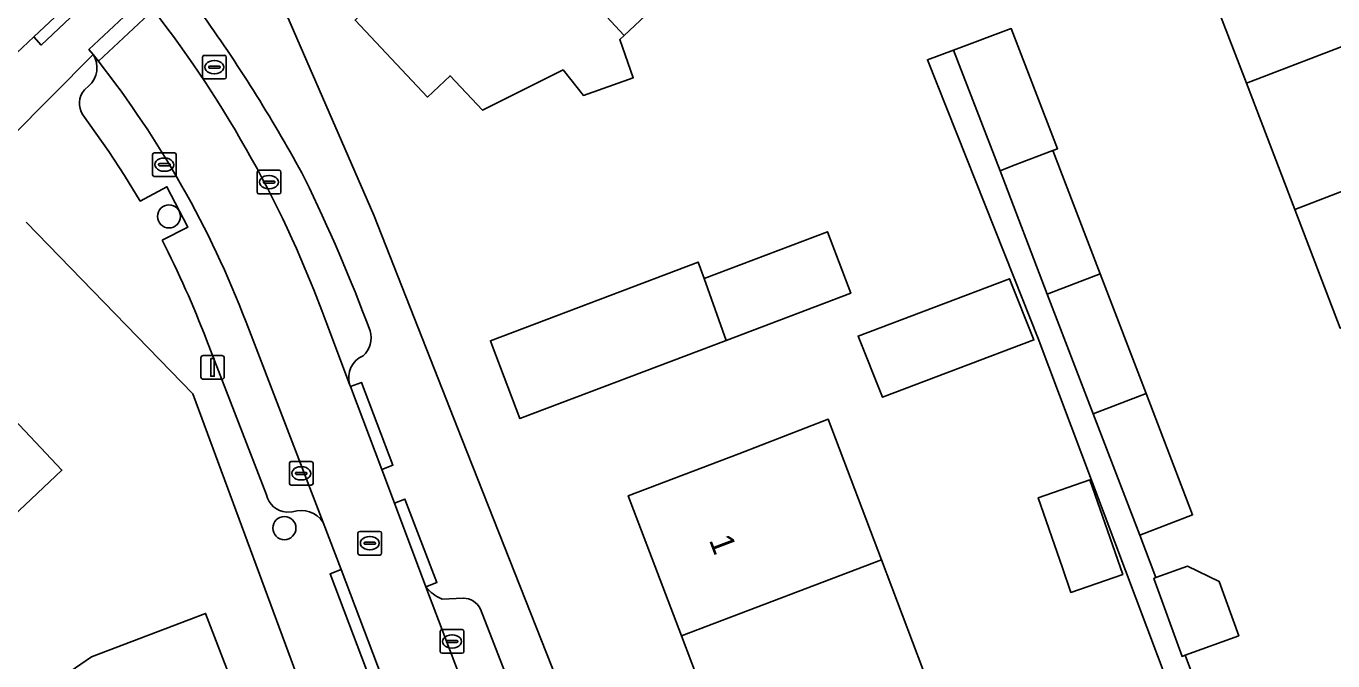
# Model space of a CAD drawing. Extents: x 159960 to 160866, y 382700 to 383354.
# Drawn here: x 160397.2 to 160452.4, y 383068.3 to 383095.2 of the extents above; entities that cross this region are included whole.
import ezdxf

# ---------------------------------------------------------------- set-up
doc = ezdxf.new("R2010")
doc.units = 0
for name, color, linetype in [('IMGEO_Boom', 7, 'Continuous'), ('IMGEO_Erf', 7, 'Continuous'), ('IMGEO_Kolk', 7, 'Continuous'), ('IMGEO_Lichtmast', 7, 'Continuous'), ('IMGEO_Pand', 7, 'Continuous'), ('IMGEO_Pand_nummerreeks', 7, 'Continuous'), ('IMGEO_Parkeervlak_open', 7, 'Continuous'), ('IMGEO_Rijbaan_lokaal_open', 7, 'Continuous'), ('IMGEO_Rioolput', 7, 'Continuous'), ('IMGEO_Voetpad_open', 7, 'Continuous')]:
    doc.layers.add(name, color=color, linetype=linetype)

msp = doc.modelspace()

# ---------------------------------------------------------------- linework, layer by layer
at = {"layer": 'IMGEO_Boom'}
for centre in [(160403.209, 383087.15), (160408.089, 383073.963)]:
    msp.add_circle(centre, 0.489, dxfattribs=at)
at = {"layer": 'IMGEO_Erf'}
for points in [[(160426.957, 383099.027), (160422.461, 383094.808), (160422.27, 383094.628), (160422.841, 383093.012), (160420.737, 383092.269), (160419.873, 383093.345), (160416.461, 383091.649), (160415.099, 383093.1), (160414.136, 383092.196), (160411.077, 383095.456)], [(160452.747, 383082.416), (160450.819, 383087.447), (160448.772, 383092.79), (160446.796, 383097.947)], [(160407.676, 383096.869), (160411.87, 383087.197), (160414.428, 383080.713), (160415.599, 383077.746), (160419.63, 383067.53)], [(160454.246, 383044.035), (160439.971, 383081.99), (160438.937, 383084.582), (160435.282, 383093.776), (160436.385, 383094.185), (160438.829, 383095.091), (160440.786, 383090.009), (160440.594, 383089.935), (160442.593, 383084.717), (160444.532, 383079.658), (160446.5, 383074.522), (160444.262, 383073.665), (160444.95, 383071.869), (160446.284, 383072.353), (160447.62, 383071.707), (160448.453, 383069.409), (160446.184, 383068.586), (160448.122, 383063.401)], [(160389.183, 383058.085), (160399.802, 383062.116), (160397.557, 383064.292), (160399.792, 383065.145), (160398.8, 383067.75), (160399.931, 383068.516), (160404.757, 383070.355), (160405.86, 383067.459), (160406.87, 383064.808), (160407.184, 383064.928), (160409.328, 383065.794), (160404.22, 383079.65), (160397.167, 383086.9)], [(160427.067, 383063.632), (160424.878, 383069.41), (160422.635, 383075.33), (160427.311, 383077.102), (160431.088, 383078.572), (160433.344, 383072.618), (160435.534, 383066.84)]]:
    msp.add_lwpolyline(points, dxfattribs=at)
for points in [[(160418.051, 383078.6), (160416.879, 383081.692), (160416.804, 383081.889), (160425.594, 383085.219), (160425.839, 383084.525), (160431.055, 383086.501), (160432.041, 383083.901), (160426.766, 383081.902)], [(160433.387, 383079.497), (160432.354, 383082.089), (160438.755, 383084.513), (160439.789, 383081.921)], [(160378.176, 383068.752), (160383.106, 383073.4), (160387.927, 383077.945), (160392.859, 383082.595), (160398.683, 383076.418), (160395.046, 383072.988), (160393.839, 383071.85), (160393.751, 383071.767), (160394.866, 383070.584), (160389.921, 383066.171), (160384.864, 383061.658), (160381.606, 383065.114)], [(160443.542, 383072.006), (160441.355, 383071.247), (160440.996, 383072.284), (160439.969, 383075.245), (160442.156, 383076.003)]]:
    msp.add_lwpolyline(points, close=True, dxfattribs=at)
at = {"layer": 'IMGEO_Kolk'}
for p, q in [((160402.513, 383088.911), (160402.513, 383089.763)), ((160402.588, 383089.837), (160403.44, 383089.837)), ((160403.001, 383089.617), (160403.026, 383089.617)), ((160403.514, 383089.763), (160403.514, 383088.911)), ((160402.772, 383089.331), (160402.772, 383089.343)), ((160403.21, 383089.294), (160402.812, 383089.294)), ((160402.815, 383089.38), (160403.213, 383089.38)), ((160403.024, 383089.057), (160402.999, 383089.057)), ((160403.256, 383089.343), (160403.256, 383089.331)), ((160406.94, 383088.175), (160406.94, 383089.027)), ((160407.015, 383089.101), (160407.867, 383089.101)), ((160407.428, 383088.881), (160407.453, 383088.881)), ((160407.941, 383089.027), (160407.941, 383088.175)), ((160403.44, 383088.837), (160402.588, 383088.837)), ((160407.199, 383088.595), (160407.199, 383088.607)), ((160407.637, 383088.558), (160407.239, 383088.558)), ((160407.242, 383088.644), (160407.64, 383088.644)), ((160407.451, 383088.321), (160407.426, 383088.321)), ((160407.683, 383088.607), (160407.683, 383088.595)), ((160407.867, 383088.101), (160407.015, 383088.101)), ((160408.301, 383075.854), (160408.301, 383076.706)), ((160408.376, 383076.78), (160409.228, 383076.78)), ((160409.302, 383076.706), (160409.302, 383075.854)), ((160408.56, 383076.274), (160408.56, 383076.286)), ((160408.998, 383076.237), (160408.6, 383076.237)), ((160408.603, 383076.323), (160409.001, 383076.323)), ((160408.789, 383076.56), (160408.814, 383076.56)), ((160409.044, 383076.286), (160409.044, 383076.274)), ((160409.228, 383075.78), (160408.376, 383075.78)), ((160408.812, 383076), (160408.787, 383076)), ((160414.68, 383068.742), (160414.68, 383069.594)), ((160414.755, 383069.668), (160415.607, 383069.668)), ((160415.681, 383069.594), (160415.681, 383068.742)), ((160414.939, 383069.162), (160414.939, 383069.174)), ((160415.377, 383069.125), (160414.979, 383069.125)), ((160414.982, 383069.211), (160415.38, 383069.211)), ((160415.168, 383069.448), (160415.193, 383069.448)), ((160415.423, 383069.174), (160415.423, 383069.162)), ((160415.607, 383068.668), (160414.755, 383068.668)), ((160415.191, 383068.888), (160415.166, 383068.888))]:
    msp.add_line(p, q, dxfattribs=at)
for points in [[(160402.513, 383088.911), (160402.513, 383089.763)], [(160402.588, 383089.837), (160403.44, 383089.837)], [(160403.514, 383089.763), (160403.514, 383088.911)], [(160406.94, 383088.175), (160406.94, 383089.027)], [(160407.015, 383089.101), (160407.867, 383089.101)], [(160407.941, 383089.027), (160407.941, 383088.175)], [(160403.44, 383088.837), (160402.588, 383088.837)], [(160407.867, 383088.101), (160407.015, 383088.101)], [(160408.301, 383075.854), (160408.301, 383076.706)], [(160408.376, 383076.78), (160409.228, 383076.78)], [(160409.302, 383076.706), (160409.302, 383075.854)], [(160409.228, 383075.78), (160408.376, 383075.78)], [(160414.68, 383068.742), (160414.68, 383069.594)], [(160414.755, 383069.668), (160415.607, 383069.668)], [(160415.681, 383069.594), (160415.681, 383068.742)], [(160415.607, 383068.668), (160414.755, 383068.668)]]:
    msp.add_lwpolyline(points, dxfattribs=at)
for centre, radius, start, end in [((160402.59, 383089.761), 0.0765, 91.552, 178.448), ((160402.59, 383089.761), 0.0765, 91.552, 178.448), ((160403.438, 383089.761), 0.0765, 1.552, 88.448), ((160403.438, 383089.761), 0.0765, 1.552, 88.448), ((160402.59, 383088.913), 0.0765, 181.552, 268.448), ((160402.59, 383088.913), 0.0765, 181.552, 268.448), ((160402.812, 383089.34), 0.0403, 85.8775, 175.7526), ((160402.809, 383089.33), 0.0366, 178.938, 274.7102), ((160403.213, 383089.337), 0.043, 264.8664, 352.4533), ((160403.217, 383089.342), 0.0386, 1.7309, 96.639), ((160403.438, 383088.913), 0.0765, 271.552, 358.448), ((160403.438, 383088.913), 0.0765, 271.552, 358.448), ((160407.017, 383089.025), 0.0765, 91.552, 178.448), ((160407.017, 383089.025), 0.0765, 91.552, 178.448), ((160407.865, 383089.025), 0.0765, 1.552, 88.448), ((160407.865, 383089.025), 0.0765, 1.552, 88.448), ((160407.239, 383088.604), 0.0403, 85.8775, 175.7526), ((160407.236, 383088.594), 0.0366, 178.938, 274.7102), ((160407.64, 383088.601), 0.043, 264.8664, 352.4533), ((160407.644, 383088.606), 0.0386, 1.7309, 96.639), ((160407.017, 383088.177), 0.0765, 181.552, 268.448), ((160407.017, 383088.177), 0.0765, 181.552, 268.448), ((160407.865, 383088.177), 0.0765, 271.552, 358.448), ((160407.865, 383088.177), 0.0765, 271.552, 358.448), ((160408.378, 383076.704), 0.0765, 91.552, 178.448), ((160408.378, 383076.704), 0.0765, 91.552, 178.448), ((160409.226, 383076.704), 0.0765, 1.552, 88.448), ((160409.226, 383076.704), 0.0765, 1.552, 88.448), ((160408.6, 383076.283), 0.0403, 85.8775, 175.7526), ((160408.597, 383076.273), 0.0366, 178.938, 274.7102), ((160409.001, 383076.28), 0.043, 264.8664, 352.4533), ((160409.005, 383076.285), 0.0386, 1.7309, 96.639), ((160408.378, 383075.856), 0.0765, 181.552, 268.448), ((160408.378, 383075.856), 0.0765, 181.552, 268.448), ((160409.226, 383075.856), 0.0765, 271.552, 358.448), ((160409.226, 383075.856), 0.0765, 271.552, 358.448), ((160414.757, 383069.592), 0.0765, 91.552, 178.448), ((160414.757, 383069.592), 0.0765, 91.552, 178.448), ((160415.605, 383069.592), 0.0765, 1.552, 88.448), ((160415.605, 383069.592), 0.0765, 1.552, 88.448), ((160414.979, 383069.171), 0.0403, 85.8775, 175.7526), ((160414.976, 383069.161), 0.0366, 178.938, 274.7102), ((160415.38, 383069.168), 0.043, 264.8664, 352.4533), ((160415.384, 383069.173), 0.0386, 1.7309, 96.639), ((160414.757, 383068.744), 0.0765, 181.552, 268.448), ((160414.757, 383068.744), 0.0765, 181.552, 268.448), ((160415.605, 383068.744), 0.0765, 271.552, 358.448), ((160415.605, 383068.744), 0.0765, 271.552, 358.448)]:
    msp.add_arc(centre, radius, start, end, dxfattribs=at)
for centre, major_axis, ratio, start_param, end_param in [((160403, 383089.337), (-0.387, 0.002), 0.722429, 4.712389, 7.853982), ((160403.025, 383089.337), (-0.39, 0.002), 0.717154, 1.570796, 4.712389), ((160407.427, 383088.601), (-0.387, 0.002), 0.722429, 4.712389, 7.853982), ((160407.452, 383088.601), (-0.39, 0.002), 0.717154, 1.570796, 4.712389), ((160408.788, 383076.28), (-0.387, 0.002), 0.722429, 4.712389, 7.853982), ((160408.813, 383076.28), (-0.39, 0.002), 0.717154, 1.570796, 4.712389), ((160415.167, 383069.168), (-0.387, 0.002), 0.722429, 4.712389, 7.853982), ((160415.192, 383069.168), (-0.39, 0.002), 0.717154, 1.570796, 4.712389)]:
    msp.add_ellipse(centre, major_axis=major_axis, ratio=ratio, start_param=start_param, end_param=end_param, dxfattribs=at)
at = {"layer": 'IMGEO_Lichtmast'}
for p, q in [((160404.555, 383080.362), (160404.555, 383081.162)), ((160404.555, 383081.162), (160404.555, 383080.362)), ((160404.655, 383081.262), (160405.445, 383081.262)), ((160405.445, 383081.262), (160404.655, 383081.262)), ((160405.545, 383081.162), (160405.545, 383080.362)), ((160405.545, 383080.362), (160405.545, 383081.162)), ((160405.445, 383080.262), (160404.655, 383080.262)), ((160404.655, 383080.262), (160405.445, 383080.262))]:
    msp.add_line(p, q, dxfattribs=at)
msp.add_lwpolyline([(160404.975, 383081.137), (160405.125, 383081.137), (160405.125, 383080.387), (160404.975, 383080.387), (160404.975, 383081.137)], dxfattribs=at)
for centre, start, end in [((160404.655, 383081.162), 90, 180), ((160404.655, 383081.162), 90, 180), ((160405.445, 383081.162), 0, 90), ((160405.445, 383081.162), 360, 90), ((160404.655, 383080.362), 180, 270), ((160404.655, 383080.362), 180, 270), ((160405.445, 383080.362), 270, 0), ((160405.445, 383080.362), 270, 0)]:
    msp.add_arc(centre, 0.1, start, end, dxfattribs=at)
at = {"layer": 'IMGEO_Pand'}
for points in [[(160422.461, 383094.808), (160426.957, 383099.027), (160425.183, 383100.917), (160419.125, 383107.369), (160414.649, 383103.168), (160419.885, 383097.59)], [(160422.461, 383094.808), (160419.885, 383097.59), (160414.649, 383103.168), (160409.479, 383098.316), (160411.655, 383095.998), (160411.077, 383095.456), (160414.136, 383092.196), (160415.099, 383093.1), (160416.461, 383091.649), (160419.873, 383093.345), (160420.737, 383092.269), (160422.841, 383093.012), (160422.27, 383094.628)], [(160458.343, 383096.468), (160457.556, 383098.521), (160457.867, 383099.219), (160457.183, 383101.001), (160456.507, 383101.303), (160456.381, 383101.631), (160446.796, 383097.947), (160448.772, 383092.79)], [(160458.343, 383096.468), (160448.772, 383092.79), (160450.819, 383087.447), (160460.412, 383091.133), (160460.11, 383091.921), (160460.421, 383092.618), (160459.822, 383094.181), (160459.095, 383094.505)], [(160438.829, 383095.091), (160436.385, 383094.185), (160438.356, 383089.077), (160438.888, 383089.281), (160440.594, 383089.935), (160440.786, 383090.009)], [(160460.412, 383091.133), (160450.819, 383087.447), (160452.747, 383082.416), (160462.339, 383086.103)], [(160440.594, 383089.935), (160438.888, 383089.281), (160438.356, 383089.077), (160440.355, 383083.859), (160442.593, 383084.717)], [(160425.839, 383084.525), (160426.766, 383081.902), (160432.041, 383083.901), (160431.055, 383086.501)], [(160425.839, 383084.525), (160425.594, 383085.219), (160416.804, 383081.889), (160416.879, 383081.692), (160418.051, 383078.6), (160426.766, 383081.902)], [(160432.354, 383082.089), (160433.387, 383079.497), (160439.789, 383081.921), (160438.755, 383084.513)], [(160442.593, 383084.717), (160440.355, 383083.859), (160442.294, 383078.801), (160444.532, 383079.658)], [(160398.683, 383076.418), (160392.859, 383082.595), (160387.927, 383077.945), (160393.751, 383071.767), (160393.839, 383071.85), (160395.046, 383072.988)], [(160444.532, 383079.658), (160442.294, 383078.801), (160444.262, 383073.665), (160446.5, 383074.522)], [(160433.344, 383072.618), (160431.088, 383078.572), (160427.311, 383077.102), (160422.635, 383075.33), (160424.878, 383069.41)], [(160439.969, 383075.245), (160440.996, 383072.284), (160441.355, 383071.247), (160443.542, 383072.006), (160442.156, 383076.003)], [(160427.067, 383063.632), (160435.534, 383066.84), (160433.344, 383072.618), (160424.878, 383069.41)], [(160444.95, 383071.869), (160444.858, 383071.836), (160446.052, 383068.538), (160446.184, 383068.586), (160448.453, 383069.409), (160447.62, 383071.707), (160446.284, 383072.353)], [(160399.931, 383068.516), (160398.8, 383067.75), (160399.792, 383065.145), (160405.86, 383067.459), (160404.757, 383070.355)]]:
    msp.add_lwpolyline(points, close=True, dxfattribs=at)
at = {"layer": 'IMGEO_Parkeervlak_open'}
for points in [[(160400.224, 383093.712), (160400.001, 383093.994)], [(160399.815, 383092.669), (160399.642, 383092.502)], [(160399.568, 383091.447), (160400.66, 383089.894), (160401.325, 383088.884), (160401.994, 383087.8), (160403.124, 383088.404), (160404.012, 383086.696), (160402.921, 383086.147)], [(160409.728, 383074.203), (160406.467, 383082.681)], [(160409.838, 383082.722), (160410.843, 383080.057)], [(160404.796, 383081.932), (160407.326, 383075.373)], [(160408.175, 383074.64), (160408.432, 383074.655)], [(160414.077, 383071.485), (160419.041, 383058.375)], [(160415.657, 383071.004), (160414.755, 383070.964)], [(160420.13, 383060.878), (160416.389, 383070.541)]]:
    msp.add_lwpolyline(points, dxfattribs=at)
for centre, radius, start, end in [((160364.13, 383066.003), 48.67, 20.0917, 37.8762), ((160351.786, 383057.856), 64.981, 28.41067, 35.52326), ((160399.131, 383093.441), 1.031, 311.5663, 32.4521), ((160366.661, 383067.435), 42.626, 20.9574, 38.0581), ((160400.255, 383091.929), 0.839, 136.9435, 215.032), ((160345.033, 383057.554), 71.125, 20.36991, 26.03584), ((160361.301, 383065.108), 46.636, 21.1464, 26.8164), ((160410.744, 383082.006), 1.014, 311.5037, 17.5037), ((160411.809, 383080.325), 1.003, 113.088, 195.4892), ((160408.253, 383075.588), 0.951, 193.0634, 265.324), ((160408.789, 383073.594), 1.12, 32.9718, 108.5742), ((160415.345, 383072.433), 1.583, 216.7963, 248.1237), ((160415.625, 383070.143), 0.862, 27.5211, 87.8511)]:
    msp.add_arc(centre, radius, start, end, dxfattribs=at)
at = {"layer": 'IMGEO_Rijbaan_lokaal_open'}
for points in [[(160403.552, 383100.436), (160405.554, 383102.316), (160415.821, 383111.942), (160411.292, 383116.793), (160405.8, 383111.613), (160397.4, 383103.731), (160393.269, 383099.855), (160387.865, 383094.781), (160375.599, 383083.221), (160380.124, 383078.379), (160390.773, 383088.421), (160397.489, 383094.742), (160399.709, 383096.829)], [(160402.547, 383095.884), (160402.323, 383096.17), (160402.15, 383096.388), (160399.824, 383094.214), (160400.001, 383093.994), (160400.224, 383093.712)]]:
    msp.add_lwpolyline(points, close=True, dxfattribs=at)
for points in [[(160402.547, 383095.884), (160400.224, 383093.712)], [(160406.467, 383082.681), (160409.728, 383074.203), (160410.485, 383072.21), (160412.619, 383066.586), (160412.657, 383066.487), (160417.616, 383053.519), (160417.972, 383052.57), (160418.386, 383051.479), (160423.026, 383039.266), (160423.192, 383038.831), (160423.203, 383038.801), (160426.171, 383039.923), (160425.991, 383040.387), (160421.337, 383052.404), (160419.77, 383056.451), (160419.498, 383057.168), (160419.041, 383058.375), (160414.077, 383071.485)], [(160414.077, 383071.485), (160412.742, 383075.024), (160412.207, 383076.443), (160410.882, 383079.95), (160410.843, 383080.057), (160409.838, 383082.722)]]:
    msp.add_lwpolyline(points, dxfattribs=at)
for centre, radius, start, end in [((160364.13, 383066.003), 48.67, 20.0917, 37.8762), ((160366.661, 383067.435), 42.626, 20.9574, 38.0581)]:
    msp.add_arc(centre, radius, start, end, dxfattribs=at)
at = {"layer": 'IMGEO_Rioolput'}
for p, q in [((160404.628, 383093.036), (160404.628, 383093.888)), ((160404.703, 383093.962), (160405.555, 383093.962)), ((160405.629, 383093.888), (160405.629, 383093.036)), ((160404.887, 383093.456), (160404.887, 383093.468)), ((160405.325, 383093.419), (160404.927, 383093.419)), ((160404.93, 383093.505), (160405.328, 383093.505)), ((160405.116, 383093.742), (160405.141, 383093.742)), ((160405.371, 383093.468), (160405.371, 383093.456)), ((160405.555, 383092.962), (160404.703, 383092.962)), ((160405.139, 383093.182), (160405.114, 383093.182)), ((160411.201, 383072.898), (160411.201, 383073.75)), ((160411.276, 383073.824), (160412.128, 383073.824)), ((160411.689, 383073.604), (160411.714, 383073.604)), ((160412.202, 383073.75), (160412.202, 383072.898)), ((160411.46, 383073.318), (160411.46, 383073.33)), ((160411.898, 383073.281), (160411.5, 383073.281)), ((160411.503, 383073.367), (160411.901, 383073.367)), ((160411.712, 383073.044), (160411.687, 383073.044)), ((160411.944, 383073.33), (160411.944, 383073.318)), ((160412.128, 383072.824), (160411.276, 383072.824))]:
    msp.add_line(p, q, dxfattribs=at)
for points in [[(160404.628, 383093.036), (160404.628, 383093.888)], [(160404.703, 383093.962), (160405.555, 383093.962)], [(160405.629, 383093.888), (160405.629, 383093.036)], [(160405.555, 383092.962), (160404.703, 383092.962)], [(160411.201, 383072.898), (160411.201, 383073.75)], [(160411.276, 383073.824), (160412.128, 383073.824)], [(160412.202, 383073.75), (160412.202, 383072.898)], [(160412.128, 383072.824), (160411.276, 383072.824)]]:
    msp.add_lwpolyline(points, dxfattribs=at)
for centre, radius, start, end in [((160404.705, 383093.886), 0.0765, 91.552, 178.448), ((160404.705, 383093.886), 0.0765, 91.552, 178.448), ((160405.553, 383093.886), 0.0765, 1.552, 88.448), ((160405.553, 383093.886), 0.0765, 1.552, 88.448), ((160404.927, 383093.465), 0.0403, 85.8775, 175.7526), ((160404.924, 383093.455), 0.0366, 178.938, 274.7102), ((160405.328, 383093.462), 0.043, 264.8664, 352.4533), ((160405.332, 383093.467), 0.0386, 1.7309, 96.639), ((160404.705, 383093.038), 0.0765, 181.552, 268.448), ((160404.705, 383093.038), 0.0765, 181.552, 268.448), ((160405.553, 383093.038), 0.0765, 271.552, 358.448), ((160405.553, 383093.038), 0.0765, 271.552, 358.448), ((160411.278, 383073.748), 0.0765, 91.552, 178.448), ((160411.278, 383073.748), 0.0765, 91.552, 178.448), ((160412.126, 383073.748), 0.0765, 1.552, 88.448), ((160412.126, 383073.748), 0.0765, 1.552, 88.448), ((160411.278, 383072.9), 0.0765, 181.552, 268.448), ((160411.278, 383072.9), 0.0765, 181.552, 268.448), ((160411.5, 383073.327), 0.0403, 85.8775, 175.7526), ((160411.497, 383073.317), 0.0366, 178.938, 274.7102), ((160411.901, 383073.324), 0.043, 264.8664, 352.4533), ((160411.905, 383073.329), 0.0386, 1.7309, 96.639), ((160412.126, 383072.9), 0.0765, 271.552, 358.448), ((160412.126, 383072.9), 0.0765, 271.552, 358.448)]:
    msp.add_arc(centre, radius, start, end, dxfattribs=at)
for centre, major_axis, ratio, start_param, end_param in [((160405.115, 383093.462), (-0.387, 0.002), 0.722429, 4.712389, 7.853982), ((160405.14, 383093.462), (-0.39, 0.002), 0.717154, 1.570796, 4.712389), ((160411.688, 383073.324), (-0.387, 0.002), 0.722429, 4.712389, 7.853982), ((160411.713, 383073.324), (-0.39, 0.002), 0.717154, 1.570796, 4.712389)]:
    msp.add_ellipse(centre, major_axis=major_axis, ratio=ratio, start_param=start_param, end_param=end_param, dxfattribs=at)
at = {"layer": 'IMGEO_Voetpad_open'}
for points in [[(160392.957, 383086.903), (160392.983, 383086.934), (160400.001, 383093.994), (160399.824, 383094.214), (160402.15, 383096.388), (160402.323, 383096.17), (160405.806, 383099.371), (160403.865, 383100.106), (160400.544, 383096.98), (160397.808, 383094.397), (160397.489, 383094.742), (160390.773, 383088.421), (160380.124, 383078.379), (160377.981, 383076.364), (160375.61, 383074.142), (160375.064, 383073.623), (160375.779, 383072.837), (160372.493, 383069.76), (160369.542, 383066.97), (160368.837, 383067.739), (160363.348, 383062.566), (160362.612, 383061.814)], [(160419.63, 383067.53), (160415.599, 383077.746), (160414.428, 383080.713), (160411.87, 383087.197), (160407.676, 383096.869), (160407.237, 383099.321), (160405.806, 383099.371), (160402.323, 383096.17)], [(160400.001, 383093.994), (160392.983, 383086.934), (160392.957, 383086.903)], [(160448.122, 383063.401), (160446.184, 383068.586), (160446.052, 383068.538), (160444.858, 383071.836), (160444.95, 383071.869), (160444.262, 383073.665), (160442.294, 383078.801), (160440.355, 383083.859), (160438.356, 383089.077), (160436.385, 383094.185), (160435.282, 383093.776), (160438.937, 383084.582), (160439.971, 383081.99), (160454.246, 383044.035)], [(160399.642, 383092.502), (160399.815, 383092.669)], [(160402.921, 383086.147), (160404.012, 383086.696), (160403.124, 383088.404), (160401.994, 383087.8), (160401.325, 383088.884), (160400.66, 383089.894), (160399.568, 383091.447)], [(160397.167, 383086.9), (160404.22, 383079.65), (160409.328, 383065.794), (160410.001, 383064.837), (160434.709, 383000), (160437.48, 382992.728), (160437.936, 382991.531), (160439.695, 382989.752), (160448.148, 382980.26), (160450.916, 382981.972)], [(160407.326, 383075.373), (160404.796, 383081.932)], [(160410.843, 383080.057), (160410.882, 383079.95), (160411.347, 383080.126), (160412.681, 383076.623), (160412.207, 383076.443), (160412.742, 383075.024), (160413.183, 383075.194), (160414.543, 383071.664), (160414.077, 383071.485)], [(160408.432, 383074.655), (160408.175, 383074.64)], [(160412.657, 383066.487), (160412.619, 383066.586), (160412.152, 383066.409), (160410.021, 383072.034), (160410.485, 383072.21), (160409.728, 383074.203)], [(160414.755, 383070.964), (160415.657, 383071.004)], [(160416.389, 383070.541), (160420.13, 383060.878)]]:
    msp.add_lwpolyline(points, dxfattribs=at)
for points in [[(160403.865, 383100.106), (160403.552, 383100.436), (160399.709, 383096.829), (160397.489, 383094.742), (160397.808, 383094.397), (160400.544, 383096.98)], [(160410.882, 383079.95), (160412.207, 383076.443), (160412.681, 383076.623), (160411.347, 383080.126)], [(160414.077, 383071.485), (160414.543, 383071.664), (160413.183, 383075.194), (160412.742, 383075.024)], [(160410.485, 383072.21), (160410.021, 383072.034), (160412.152, 383066.409), (160412.619, 383066.586)]]:
    msp.add_lwpolyline(points, close=True, dxfattribs=at)
for centre, radius, start, end in [((160351.786, 383057.856), 64.981, 28.41067, 35.52326), ((160399.131, 383093.441), 1.031, 311.5663, 32.4521), ((160400.255, 383091.929), 0.839, 136.9435, 215.032), ((160345.033, 383057.554), 71.125, 20.36991, 26.03584), ((160361.301, 383065.108), 46.636, 21.1464, 26.8164), ((160410.744, 383082.006), 1.014, 311.5037, 17.5037), ((160411.809, 383080.325), 1.003, 113.088, 195.4892), ((160408.253, 383075.588), 0.951, 193.0634, 265.324), ((160408.789, 383073.594), 1.12, 32.9718, 108.5742), ((160415.345, 383072.433), 1.583, 216.7963, 248.1237), ((160415.625, 383070.143), 0.862, 27.5211, 87.8511)]:
    msp.add_arc(centre, radius, start, end, dxfattribs=at)

# ---------------------------------------------------------------- texts
at = {"layer": 'IMGEO_Pand_nummerreeks'}
msp.add_text('1', height=1, rotation=290.7518, dxfattribs=at).set_placement((160426.038, 383073.462))

doc.saveas('drawing.dxf')
